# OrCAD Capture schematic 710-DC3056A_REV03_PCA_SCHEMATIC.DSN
size B; title: 3.3V to 1.2V at 12.5A, 2MHz Automotive Low EMI Buck Regulator in a 1.22CM2 Solution; rev: 02
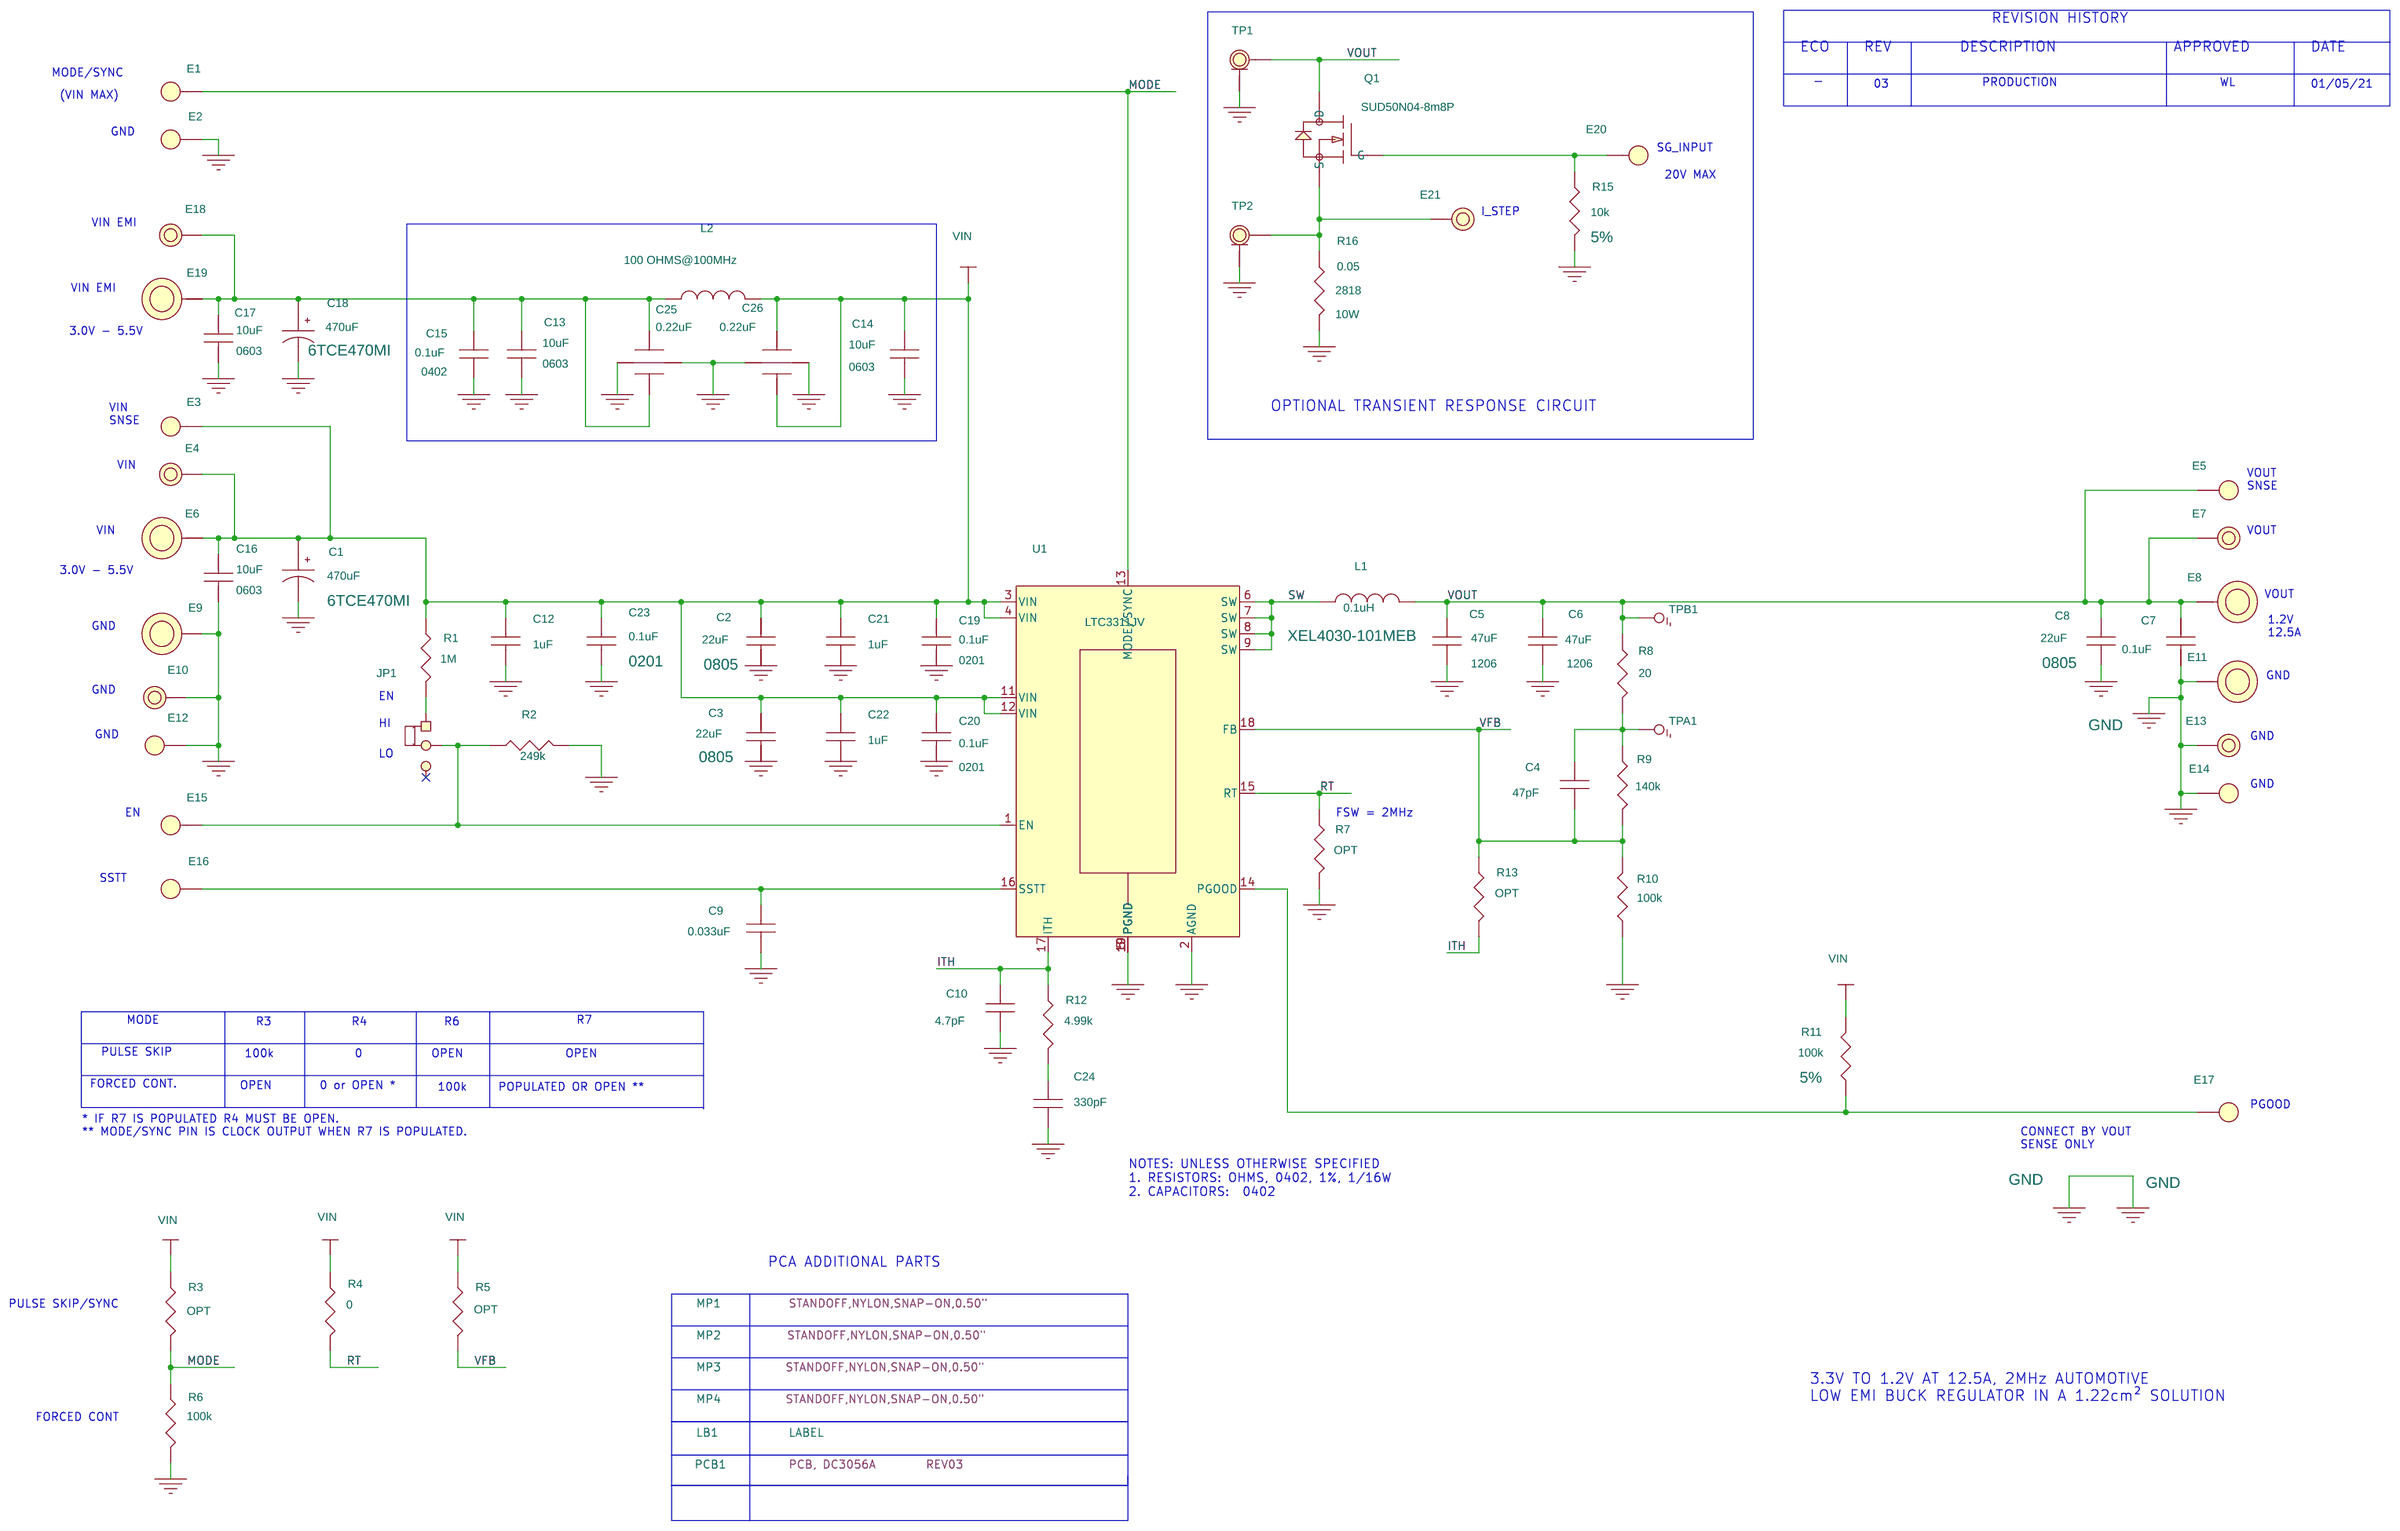
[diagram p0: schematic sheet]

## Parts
C1  470uF  [CAPMP7343N]
C2  22uF  [CC0805N]
C3  22uF  [CC0805N]
C4  47pF  [CC0402N]
C5  47uF  [CC1206N]
C6  47uF  [CC1206N]
C7  0.1uF  [CC0402N]
C8  22uF  [CC0805N]
C9  0.033uF  [CC0402N]
C10  4.7pF  [CC0402N]
C12  1uF  [CC0402N]
C13  10uF  [CC0603N]
C14  10uF  [CC0603N]
C15  0.1uF  [CC0402N]
C16  10uF  [CC0603N]
C17  10uF  [CC0603N]
C18  470uF  [CAPMP7343N]
C19  0.1uF  [CC0201M]
C20  0.1uF  [CC0201M]
C21  1uF  [CC0402N]
C22  1uF  [CC0402N]
C23  0.1uF  [CC0201M]
C24  330pF  [CC0402N]
C25  0.22uF  [JOHANSON-X2Y-X14]
C26  0.22uF  [JOHANSON-X2Y-X14]
E1  TEST POINT  [MILLMAX2308]
E2  TEST POINT  [MILLMAX2308]
E3  TEST POINT  [MILLMAX2308]
E4  TEST POINT  [MILLMAX2501]
E5  TEST POINT  [MILLMAX2308]
E6  BANANA JACK  [KEY-575-4]
E7  TEST POINT  [MILLMAX2501]
E8  BANANA JACK  [KEY-575-4]
E9  BANANA JACK  [KEY-575-4]
E10  TEST POINT  [MILLMAX2501]
E11  BANANA JACK  [KEY-575-4]
E12  TEST POINT  [MILLMAX2308]
E13  TEST POINT  [MILLMAX2501]
E14  TEST POINT  [MILLMAX2308]
E15  TEST POINT  [MILLMAX2308]
E16  TEST POINT  [MILLMAX2308]
E17  TEST POINT  [MILLMAX2308]
E18  TEST POINT  [MILLMAX2501]
E19  BANANA JACK  [KEY-575-4]
E20  TEST POINT  [MILLMAX2308]
E21  TEST POINT  [MILLMAX2501]
JP1  HDR  [HD1X3-079]
L1  0.1uH  [COILCRAFT-XEL4030]
L2  100 OHMS@100MHz  [WURTH-74279226101]
LB1  LABEL  [895-0154_REV01]
MP1  STANDOFF  [KEYSTONE_8829-8834]
MP2  STANDOFF  [KEYSTONE_8829-8834]
MP3  STANDOFF  [KEYSTONE_8829-8834]
MP4  STANDOFF  [KEYSTONE_8829-8834]
PCB1  PCB, DC3056A
Q1  SUD50N04-8m8P  [TO-252-3N]
R1  1M  [CR0402N]
R2  249k  [CR0402N]
R3  OPT  [CR0402N]
R4  0  [CR0402N]
R5  OPT  [CR0402N]
R6  100k  [CR0402N]
R7  OPT  [CR0402N]
R8  20  [CR0402N]
R9  140k  [CR0402N]
R10  100k  [CR0402N]
R11  100k  [CR0402N]
R12  4.99k  [CR0402N]
R13  OPT  [CR0402N]
R15  10k  [CR0402N]
R16  0.05  [VISHAY-WSHP2818]
TP1  TEST JACK  [TELEDYNE-PK5-2.5MM-113_ALT1]
TP2  TEST JACK  [TELEDYNE-PK5-2.5MM-113_ALT1]
TPA1  COPPER FEATURE PAD  [PADSTYLE1]
TPB1  COPPER FEATURE PAD  [PADSTYLE1]
U1  LTC3311JV  [LTC-LQFN-18-1548]
XJP4  SHUNT

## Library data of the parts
C1 C18 = CAP_P_ALT: CAP.,470uF,TANT POLY,6.3V,20%,7343; CLASS: DISCRETE; Dielectric Type: TANT POLY; Inventory Qty: 5001; Manufacturer: PANASONIC; Manufacturer PN: 6TCE470MI; PART_NUMBER: 150-0805; Package Size: 7343; Package Type: Surface Mount; Rated Voltage: 6.3V; Tolerance: 20%
C2 C3 C8 = CAP: CAP.,22uF,X7S,6.3V,20%,0805; CLASS: DISCRETE; Dielectric Type: X7S; Inventory Qty: 12300; Manufacturer: TDK; Manufacturer PN: C2012X7S0J226M125AC; PART_NUMBER: 150-0806; Package Size: 0805; Rated Voltage: 6.3V; Temperature Coefficient: X7S; Tolerance: 20%
C4 = CAP: CAP.,47pF,C0G/NP0,50V,5%,0402; CLASS: DISCRETE; Dielectric Type: C0G/NP0; FPLIST: CC0402N,CC0402L,CC0402M; Inventory Qty: 20102; Manufacturer: KEMET; Manufacturer PN: C0402C470J5GAC7867; PART_NUMBER: 150-0107; Package Size: 0402; Rated Voltage: 50V; Tolerance: 5%
C5 C6 = CAP: CAP.,47uF,X7S,6.3V,20%,1206,NO SUBS. ALLOWED; CLASS: DISCRETE; Dielectric Type: X7S; FPLIST: CC1206N,CC1206L,CC1206M; Inventory Qty: 7200; Manufacturer: TDK; Manufacturer PN: C3216X7S0J476M160AC; PART_NUMBER: 150-2602; Package Size: 1206; Rated Voltage: 6.3V; Tolerance: 20%
C7 C15 = CAP: CAP.,0.1uF,X7R,50V,10%,0402,AEC-Q200; CLASS: DISCRETE; Dielectric Type: X7R; FPLIST: CC0402N,CC0402L,CC0402M; Inventory Qty: 74330; Manufacturer: MURATA; Manufacturer PN: GCM155R71H104KE02D; PART_NUMBER: 150-2620; Package Size: 0402; Rated Voltage: 50V; Temperature Coefficient: X7R; Tolerance: 10%
C9 = CAP: CAP.,0.033uF,X7R,25V,10%,0402; CLASS: DISCRETE; Dielectric Type: X7R; FPLIST: CC0402N,CC0402L,CC0402M; Inventory Qty: 27937; Manufacturer: KEMET; Manufacturer PN: C0402C333K3RACTU; PART_NUMBER: 150-0484; Package Size: 0402; Rated Voltage: 25V; Tolerance: 10%
C10 = CAP: CAP.,4.7pF,C0G,50V,+/-0.25pF,0402; CLASS: DISCRETE; Dielectric Type: C0G; FPLIST: CC0402N,CC0402L,CC0402M; Inventory Qty: 9760; Manufacturer: AVX; Manufacturer PN: 04025A4R7CAT2A; PART_NUMBER: 150-1668; Package Size: 0402; Package Type: SMD; Rated Voltage: 50V; Tolerance: +/-0.25pF
C12 C21 C22 = CAP: CAP.,1uF,X7S,10V,10%,0402,AEC-Q200,NO SUBS. ALLOWED; CLASS: DISCRETE; Dielectric Type: X7S; FPLIST: CC0402N,CC0402L,CC0402M; Inventory Qty: 10000; Manufacturer: MURATA; Manufacturer PN: GCM155C71A105KE38D; PART_NUMBER: 150-0594; Package Size: 0402; Rated Voltage: 10V; Temperature Coefficient: X7S; Tolerance: 10%
C13 C14 C16 C17 = CAP: CAP.,10uF,X7S,6.3V,20%,0603; CLASS: DISCRETE; Dielectric Type: X7S; FPLIST: CC0603N,CC0603L,CC0603M; Inventory Qty: 34800; Manufacturer: TDK; Manufacturer PN: C1608X7S0J106M080AC; PART_NUMBER: 150-1745; Package Size: 0603; Rated Voltage: 6.3V; Tolerance: 20%
C19 C20 = CAP: CAP.,0.1uF,X7S,16V,10%,0201; CLASS: DISCRETE; Dielectric Type: X7S; FPLIST: CC0201N,CC0201L,CC0201M; Inventory Qty: 73200; Manufacturer: MURATA; Manufacturer PN: GRM033C71C104KE14D; PART_NUMBER: 150-0807; Package Size: 0201; Rated Voltage: 16V; Temperature Coefficient: X7S; Tolerance: 10%
C23 = CAP: CAP.,0.1uF,X7S,16V,10%,0201; CLASS: DISCRETE; Dielectric Type: X7S; Inventory Qty: 73200; Manufacturer: MURATA; Manufacturer PN: GRM033C71C104KE14D; PART_NUMBER: 150-0807; Package Size: 0201; Rated Voltage: 16V; Temperature Coefficient: X7S; Tolerance: 10%
C24 = CAP: CAP.,330pF,C0G,50V,5%,0402; CLASS: DISCRETE; Dielectric Type: C0G; FPLIST: CC0402N,CC0402L,CC0402M; Inventory Qty: 25881; Manufacturer: MURATA; Manufacturer PN: GRM1555C1H331JA01D; PART_NUMBER: 150-0056; Package Size: 0402; Rated Voltage: 50V; Tolerance: 5%
C25 C26 = JOHANSON-X2Y: CAP.,0.22uF,X7R,6.3V,20%,0603; CLASS: DISCRETE; Dielectric Type: X7R; Inventory Qty: 12000; Manufacturer: JOHANSON DIELECTRICS; Manufacturer PN: 6R3X14W224MV4T; PART_NUMBER: 150-0876; Package Size: 0603; Rated Voltage: 6.3V; Temperature Coefficient: X7R; Tolerance: 20%
E1-E3 E5 E12 E14-E17 E20 = TEST_POINT_.156_MILL-MAX_2308: TEST POINT,TURRET,0.064" MTG. HOLE,PCB 0.062" THK; CLASS: IO; Inventory Qty: 1142083; Manufacturer PN: 2308-2-00-80-00-00-07-0; PART_NUMBER: 260-0004
E4 E7 E10 E13 E18 = TESTPOINT_.219_MILL-MAX_2501: TEST POINT,TURRET,0.094" MTG. HOLE,PCB 0.062" THK; CLASS: IO; Inventory Qty: 823526; Manufacturer: MILL-MAX; Manufacturer PN: 2501-2-00-80-00-00-07-0; PART_NUMBER: 260-0003
E6 E8 E9 E11 E19 = BANANA_KEYSTONE-575-4: CONN.,BANANA JACK,FEMALE,THT,NON-INSULATED,SWAGE,0.218"; CLASS: IO; Inventory Qty: 203061; Manufacturer: KEYSTONE; Manufacturer PN: 575-4; PART_NUMBER: 250-0428
E21 = TESTPOINT_.219_MILL-MAX_2501: TEST POINT,TURRET,0.094" MTG. HOLE,PCB 0.062" THK; CLASS: IO; FPLIST: MILLMAX2501,MILLMAX2501_ALT1; Inventory Qty: 823526; Manufacturer: MILL-MAX; Manufacturer PN: 2501-2-00-80-00-00-07-0; PART_NUMBER: 260-0003
JP1 = 3_PIN_HEADER_.079_SINGLE_ROW_D: CONN.,HDR,MALE,1x3,2mm,VERT,ST,THT; CLASS: IO; Inventory Qty: 22043; Manufacturer: Wurth Elektronik; Manufacturer PN: 62000311121; PART_NUMBER: 250-0484
L1 = IND_ALT: IND.,0.1uH,PWR,SHIELDED,20%,25.8A,1.8mOhms,4.3x4.3mm,XEL4030,AEC-Q200; CLASS: DISCRETE; Inventory Qty: 2103; Manufacturer: COILCRAFT; Manufacturer PN: XEL4030-101MEB; PART_NUMBER: 200-0670; Package Size: 4.3x4.3mm,XEL4030; Tolerance: 20%
L2 = IND_ALT: IND.,100 OHMS@100MHz,FERRITE BEAD,25%,8A,6mOHMS,1812; CLASS: DISCRETE; Inventory Qty: 3043; Manufacturer: WURTH ELEKTRONIK; Manufacturer PN: 74279226101; PART_NUMBER: 200-0280; Package Size: 1812; Tolerance: 25%
LB1 = BLANK_LABEL: LABEL SPEC, DEMO BOARD SERIAL NUMBER; Inventory Qty: 0; Manufacturer: BRADY; Manufacturer PN: THT-96-717-10; PART_NUMBER: 895-0154
MP1-MP4 = BLANK_MECHANICAL_PART: STANDOFF,NYLON,SNAP-ON,0.50"; CLASS: DISCRETE; FPLIST: KEYSTONE_8829-8834,MTG-8831; Inventory Qty: 214842; Manufacturer: KEYSTONE; Manufacturer PN: 8833; PART_NUMBER: 763-0007
PCB1 = BLANK_PCB_PART: BOM Notes: REV03; CLASS: DISCRETE; Inventory Qty: 0; Manufacturer: ADI APPROVED SUPPLIER; Manufacturer PN: 600-DC3056A; PART_NUMBER: 600-DC3056A
Q1 = 3P_N-CH_TYPE2A: XSTR.,MOSFET,N-CH,40V,14A,DPAK (TO-252); CLASS: DISCRETE; FPLIST: TO-252-3N,TO-252-3L,TO-252-3M; Inventory Qty: 44191; Manufacturer: VISHAY; Manufacturer PN: SUD50N04-8M8P-4GE3; PART_NUMBER: 240-0021; Package Type: DPAK (TO-252); Rated Voltage: 40V
R1 = RES: RES.,1M OHMS,1%,1/16W,0402,AEC-Q200; CLASS: DISCRETE; FPLIST: CR0402N,CR0402L,CR0402M; Inventory Qty: 86432; Manufacturer: STACKPOLE ELECTRONICS, INC.; Manufacturer PN: RMCF0402FT1M00; PART_NUMBER: 100-2457; Package Size: 0402; Rated Power: 1/16W; Temperature Coefficient: 100ppm; Tolerance: 1%
R2 = RES: RES.,249k OHMS,1%,1/16W,0402,AEC-Q200; CLASS: DISCRETE; FPLIST: CR0402N,CR0402L,CR0402M; Inventory Qty: 26713; Manufacturer: NIC; Manufacturer PN: NRC04F2493TRF; PART_NUMBER: 100-2663; Package Size: 0402; Rated Power: 1/16W; Temperature Coefficient: 100ppm; Tolerance: 1%
R3 R5 R7 R13 = RES: RES., OPTION, 0402; CLASS: DISCRETE; FPLIST: CR0402N,CR0402L,CR0402M; PART_NUMBER: 100-0357; Package Size: 0402
R4 = RES: RES.,0 OHM,1/16W,0402,AEC-Q200; CLASS: DISCRETE; FPLIST: CR0402N,CR0402L,CR0402M; Inventory Qty: 127940; Manufacturer: NIC; Manufacturer PN: NRC04ZOTRF; PART_NUMBER: 100-2023; Package Size: 0402; Rated Power: 1/16W
R6 R11 = RES: RES.,100k OHMS,5%,1/16W,0402,AEC-Q200; CLASS: DISCRETE; FPLIST: CR0402N,CR0402L,CR0402M; Inventory Qty: 59032; Manufacturer: NIC; Manufacturer PN: NRC04J104TRF; PART_NUMBER: 100-0359; Package Size: 0402; Rated Power: 1/16W; Temperature Coefficient: 200ppm/C; Tolerance: 5%
R8 = RES: RES.,20 OHMS,1%,1/16W,0402,AEC-Q200; CLASS: DISCRETE; FPLIST: CR0402N,CR0402L,CR0402M; Inventory Qty: 29845; Manufacturer: NIC; Manufacturer PN: NRC04F20R0TRF; PART_NUMBER: 100-0250; Package Size: 0402; Rated Power: 1/16W; Temperature Coefficient: 100ppm; Tolerance: 1%
R9 = RES: RES.,140k OHMS,1%,1/16W,0402,AEC-Q200; CLASS: DISCRETE; FPLIST: CR0402N,CR0402L,CR0402M; Inventory Qty: 70827; Manufacturer: NIC; Manufacturer PN: NRC04F1403TRF; PART_NUMBER: 100-2880; Package Size: 0402; Rated Power: 1/16W; Temperature Coefficient: 100ppm; Tolerance: 1%
R10 = RES: RES.,100k OHMS,1%,1/16W,0402,AEC-Q200; CLASS: DISCRETE; FPLIST: CR0402N,CR0402L,CR0402M; Inventory Qty: 150967; Manufacturer: VISHAY; Manufacturer PN: CRCW0402100KFKED; PART_NUMBER: 100-2396; Package Size: 0402; Rated Power: 1/16W; Temperature Coefficient: 100ppm; Tolerance: 1%
R12 = RES: RES.,4.99k OHMS,1%,1/16W,0402; CLASS: DISCRETE; FPLIST: CR0402N,CR0402L,CR0402M; Inventory Qty: 102670; Manufacturer: NIC; Manufacturer PN: NRC04F4991TRF; PART_NUMBER: 100-2625; Package Size: 0402; Rated Power: 1/16W; Temperature Coefficient: 100ppm/C; Tolerance: 1%
R15 = RES: RES.,10k OHMS,5%,1/16W,0402,AEC-Q200; CLASS: DISCRETE; Inventory Qty: 64117; Manufacturer: NIC; Manufacturer PN: NRC04J103TRF; PART_NUMBER: 100-0214; Package Size: 0402; Rated Power: 1/16W; Temperature Coefficient: 200ppm; Tolerance: 5%
R16 = RES: RES.,0.05 OHMS,1%,10W,2818,AEC-Q200,METAL,HP; CLASS: DISCRETE; Inventory Qty: 4750; Manufacturer: VISHAY; Manufacturer PN: WSHP2818R0500FEA; PART_NUMBER: 100-1684; Package Size: 2818; Rated Power: 10W; Temperature Coefficient: +/-75ppm; Tolerance: 1%
TP1 TP2 = TELEDYNE-PK5-2.5MM-113_ALT1: CONN.,TEST JACK,PLUG,1POS,THT,VERT; CLASS: IO; Inventory Qty: 0; Manufacturer: TELEDYNE; Manufacturer PN: PK5-2.5MM-113; PART_NUMBER: 250-1016
TPA1 TPB1 = PAD_SMALL_FILLED: TESTPOINT, PCB COPPER FEATURE; CLASS: IO; Manufacturer: N/A; Manufacturer PN: N/A; PART_NUMBER: PCBPADS-11
U1 = LTC3311JV: IC,Low Voltage Syn.Stepdown Reg,LQFN-18; CLASS: IC; Inventory Qty: 0; Manufacturer: ANALOG DEVICES; Manufacturer PN: LTC3311JV#PBF; PART_NUMBER: LTC3311JV#PBF; Package Size: 18-LQFN; Package Type: LQFN-18
XJP4 = CONN_SHUNT_2_POS_2mm: CONN.,SHUNT,FEMALE,2 POS,2mm; CLASS: IO; Inventory Qty: 64675; Manufacturer: Wurth Elektronik; Manufacturer PN: 60800213421; PART_NUMBER: 250-0485

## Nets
GND: C1.2 C2.2 C3.2 C5.2 C6.2 C7.2 C8.2 C9.2 C10.2 C12.2 C13.2 C14.2 C15.2 C16.2 C17.2 C18.2 C19.2 C20.2 C21.2 C22.2 C23.2 C24.2 C25.3(G1) C25.4(G2) C26.3(G1) C26.4(G2) E2.1(A) E9.1 E10.1 E11.1 E12.1(A) E13.1 E14.1(A) R2.2 R6.2 R7.2 R10.1 R15.2 R16.2 TP1.2(GND) TP1.3(GND) TP1.4(GND) TP1.5(GND) TP2.2(GND) TP2.3(GND) TP2.4(GND) TP2.5(GND) U1.2(AGND) U1.5(PGND) U1.10(PGND) U1.19(PGND)
VIN: C1.1 C2.1 C3.1 C12.1 C14.1 C16.1 C19.1 C20.1 C21.1 C22.1 C23.1 C26.1(A) C26.2(B) E3.1(A) E4.1 E6.1 L2.2 R1.1 R3.1 R4.1 R5.1 R11.1 U1.3(VIN) U1.4(VIN) U1.11(VIN) U1.12(VIN)
ITH: C10.1 R12.1 R13.2 U1.17(ITH)
MODE: E1.1(A) R3.2 R6.1 U1.13(MODE/SYNC)
RT: R4.2 R7.1 U1.15(RT)
SW: L1.1 U1.6(SW) U1.7(SW) U1.8(SW) U1.9(SW)
VFB: C4.2 R5.2 R9.2 R10.2 R13.1 U1.18(FB)
VOUT: C5.1 C6.1 C7.1 C8.1 E5.1(A) E7.1 E8.1 L1.2 Q1.2(D) R8.1 TP1.1 TPB1.1
N16777546: E15.1(A) JP1.2 R2.1 U1.1(EN)
N16777612: C4.1 R8.2 R9.1 TPA1.1
N16777640: E17.1(A) R11.2 U1.14(PGOOD)
N16777650: C24.1 R12.2
N16777742: JP1.1 R1.2
N16777770: C9.1 E16.1(A) U1.16(SSTT)
N16814255: C13.1 C15.1 C17.1 C18.1 C25.1(A) C25.2(B) E18.1 E19.1 L2.1
N16841248: E20.1(A) Q1.1(G) R15.1
N16841255: E21.1 Q1.3(S) R16.1 TP2.1

Not connected (* = marked no-connect by the designer): JP1 3*

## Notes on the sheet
- REVISION HISTORY
- ECO
- REV
- DESCRIPTION
- APPROVED
- DATE
- MODE/SYNC
- -
- PRODUCTION
- WL
- (VIN MAX)
- 03
- 01/05/21
- GND
- SG_INPUT
- 20V MAX
- I_STEP
- VIN EMI
- VIN EMI
- 3.0V - 5.5V
- VIN
  SNSE
- OPTIONAL TRANSIENT RESPONSE CIRCUIT
- VIN
- VOUT
  SNSE
- VIN
- VOUT
- 3.0V - 5.5V
- VOUT
- GND
- 1.2V
  12.5A
- GND
- GND
- EN
- GND
- HI
- GND
- LO
- GND
- EN
- FSW = 2MHz
- SSTT
- MODE
- R3
- R4
- R6
- R7
- PULSE SKIP
- 100k
- 0
- OPEN
- OPEN
- FORCED CONT.
- OPEN
- 0 or OPEN *
- 100k
- POPULATED OR OPEN **
- PGOOD
- * IF R7 IS POPULATED R4 MUST BE OPEN.
  ** MODE/SYNC PIN IS CLOCK OUTPUT WHEN R7 IS POPULATED.
- CONNECT BY VOUT
  SENSE ONLY
- NOTES: UNLESS OTHERWISE SPECIFIED
  1. RESISTORS: OHMS, 0402, 1%, 1/16W
  2. CAPACITORS:  0402
- PCA ADDITIONAL PARTS
- PULSE SKIP/SYNC
- 3.3V TO 1.2V AT 12.5A, 2MHz AUTOMOTIVE
  LOW EMI BUCK REGULATOR IN A 1.22cm² SOLUTION
- FORCED CONT
